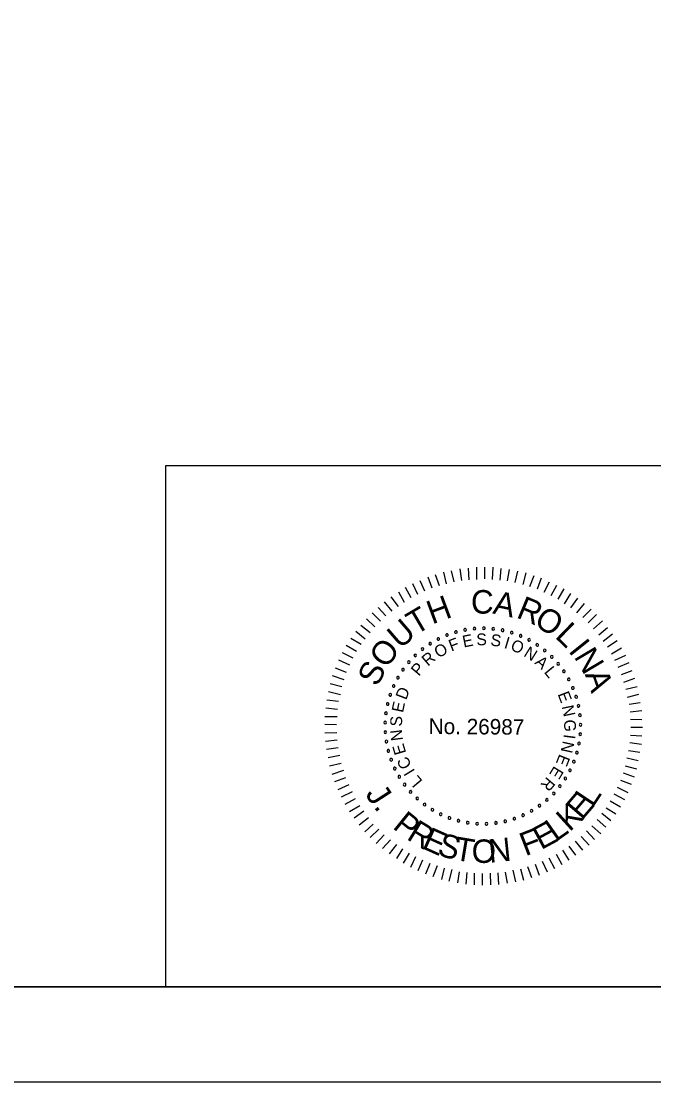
# Model space of a CAD drawing. Extents: x -125.5 to -89.4, y -5.1 to 16.9.
# Drawn here: x -103.66 to -100.32, y -5.07 to 0.53 of the extents above; entities that cross this region are included whole.
import ezdxf

# ---------------------------------------------------------------- set-up
doc = ezdxf.new("R2010")
doc.units = 0
for name, color, linetype in [('BR_BORDER LINES', 7, 'Continuous'), ('BR_TABLE LINES', 7, 'Continuous'), ('BR_TEXT', 7, 'Continuous'), ('Level 31', 7, 'Continuous')]:
    doc.layers.add(name, color=color, linetype=linetype)

msp = doc.modelspace()

# ---------------------------------------------------------------- linework, layer by layer
at = {"layer": 'BR_BORDER LINES'}
for p, q in [((-102.8989, -1.8161), (-97.5337, -1.8161)), ((-102.8989, -4.5661), (-102.8989, -1.8161)), ((-123.6994, -4.5662), (-90.0334, -4.5662))]:
    msp.add_line(p, q, dxfattribs=at)
at = {"layer": 'BR_TABLE LINES'}
msp.add_lwpolyline([(-123.6994, 16.4338), (-90.0334, 16.4338), (-90.0334, -4.5662), (-123.6994, -4.5662)], close=True, dxfattribs=at)
at = {"layer": 'BR_TEXT'}
for p, q in [((-101.4937, -2.4629), (-101.5147, -2.4044)), ((-101.4541, -2.4504), (-101.476, -2.3927)), ((-101.418, -2.4404), (-101.4312, -2.3793)), ((-101.3767, -2.4304), (-101.3908, -2.3711)), ((-101.3372, -2.423), (-101.3461, -2.362)), ((-101.2977, -2.419), (-101.3015, -2.3581)), ((-101.2582, -2.4168), (-101.2576, -2.3524)), ((-101.2161, -2.4146), (-101.2156, -2.3528)), ((-101.1741, -2.4175), (-101.1718, -2.3531)), ((-101.1338, -2.4204), (-101.129, -2.3595)), ((-101.0952, -2.425), (-101.0844, -2.3642)), ((-101.0549, -2.4331), (-101.0407, -2.374)), ((-101.0138, -2.4437), (-100.9979, -2.3829)), ((-100.977, -2.4543), (-100.9551, -2.397)), ((-101.604, -2.5144), (-101.6344, -2.46)), ((-101.5695, -2.4966), (-101.5957, -2.4406)), ((-101.5325, -2.4798), (-101.556, -2.4238)), ((-100.9376, -2.4675), (-100.9157, -2.4093)), ((-100.9017, -2.485), (-100.8738, -2.4294)), ((-100.8658, -2.5024), (-100.8345, -2.4469)), ((-101.6704, -2.5593), (-101.7095, -2.5083)), ((-101.6394, -2.5381), (-101.6698, -2.4838)), ((-100.8282, -2.5208), (-100.796, -2.467)), ((-100.795, -2.5451), (-100.761, -2.4913)), ((-100.7617, -2.5668), (-100.7252, -2.5165)), ((-101.7369, -2.6094), (-101.7786, -2.5644)), ((-101.7041, -2.5847), (-101.744, -2.5346)), ((-100.7293, -2.5928), (-100.6886, -2.5434)), ((-101.7958, -2.6673), (-101.8392, -2.6248)), ((-101.7663, -2.6366), (-101.8106, -2.5925)), ((-100.6977, -2.618), (-100.6545, -2.5737)), ((-100.6697, -2.6456), (-100.6264, -2.6022)), ((-101.8209, -2.6988), (-101.8704, -2.6598)), ((-100.6416, -2.6768), (-100.594, -2.6351)), ((-100.6144, -2.7088), (-100.5677, -2.6705)), ((-101.8686, -2.761), (-101.9224, -2.728)), ((-101.8469, -2.732), (-101.8964, -2.6922)), ((-100.5906, -2.7424), (-100.5414, -2.7033)), ((-100.5686, -2.7718), (-100.516, -2.7396)), ((-101.893, -2.7977), (-101.9467, -2.7656)), ((-100.5466, -2.8089), (-100.4931, -2.7776)), ((-101.9279, -2.8687), (-101.9852, -2.8433)), ((-101.9104, -2.8319), (-101.9668, -2.804)), ((-100.5288, -2.8433), (-100.4711, -2.8164)), ((-101.9454, -2.9072), (-102.0035, -2.8852)), ((-100.5111, -2.8804), (-100.4543, -2.856)), ((-100.4943, -2.9192), (-100.4374, -2.8982)), ((-101.9577, -2.9474), (-102.0193, -2.9246)), ((-100.4809, -2.9596), (-100.4232, -2.9378)), ((-101.9772, -3.0253), (-102.0397, -3.0094)), ((-101.97, -2.9833), (-102.0308, -2.9682)), ((-100.4708, -2.9957), (-100.4107, -2.9816)), ((-101.9878, -3.0613), (-102.0487, -3.0531)), ((-100.4626, -3.0378), (-100.4024, -3.0229)), ((-100.4543, -3.074), (-100.3951, -3.0667)), ((-101.9925, -3.1024), (-102.0542, -3.0951)), ((-100.4478, -3.1152), (-100.3868, -3.1088)), ((-101.9974, -3.183), (-102.06, -3.1825)), ((-101.9954, -3.1419), (-102.0597, -3.1414)), ((-100.4464, -3.1547), (-100.3863, -3.1552)), ((-101.9961, -3.226), (-102.0604, -3.2272)), ((-100.4471, -3.2388), (-100.3871, -3.241)), ((-100.4442, -3.1959), (-100.3833, -3.1964)), ((-101.9938, -3.2646), (-102.0556, -3.2718)), ((-100.4492, -3.2774), (-100.3883, -3.2856)), ((-101.9898, -3.3058), (-102.0509, -3.3148)), ((-101.9799, -3.3454), (-102.0426, -3.3586)), ((-100.4564, -3.3185), (-100.3972, -3.3284)), ((-101.9733, -3.3875), (-102.0344, -3.4016)), ((-100.4742, -3.3999), (-100.4143, -3.415)), ((-100.4653, -3.3579), (-100.4053, -3.3721)), ((-101.9616, -3.4245), (-102.0236, -3.4454)), ((-101.95, -3.4632), (-102.0085, -3.4842)), ((-100.4848, -3.4367), (-100.4275, -3.4586)), ((-101.9331, -3.5003), (-101.9908, -3.5272)), ((-100.5163, -3.512), (-100.4599, -3.5399)), ((-100.4989, -3.4752), (-100.4424, -3.4971)), ((-101.9162, -3.5364), (-101.9731, -3.566)), ((-101.8994, -3.5735), (-101.9537, -3.6048)), ((-100.5346, -3.5479), (-100.4774, -3.5784)), ((-101.8756, -3.6106), (-101.93, -3.6419)), ((-100.5756, -3.6213), (-100.5235, -3.6535)), ((-100.553, -3.5846), (-100.5, -3.6168)), ((-101.8544, -3.6399), (-101.9045, -3.6764)), ((-101.829, -3.6736), (-101.8791, -3.7127)), ((-100.6224, -3.6836), (-100.5764, -3.7234)), ((-100.5981, -3.6503), (-100.5495, -3.6876)), ((-101.8043, -3.7073), (-101.8485, -3.7481)), ((-101.7754, -3.7333), (-101.8204, -3.7784)), ((-100.6787, -3.7423), (-100.6362, -3.7882)), ((-100.6502, -3.7168), (-100.6033, -3.7584)), ((-101.7465, -3.7636), (-101.7889, -3.8095)), ((-101.714, -3.7895), (-101.7548, -3.8364)), ((-100.7392, -3.7976), (-100.6993, -3.8452)), ((-100.7073, -3.7721), (-100.6648, -3.8188)), ((-101.6808, -3.8156), (-101.7207, -3.8633)), ((-101.6501, -3.8373), (-101.6814, -3.8894)), ((-100.8057, -3.8443), (-100.7727, -3.8969)), ((-100.772, -3.8231), (-100.7364, -3.8714)), ((-101.6151, -3.8599), (-101.6464, -3.9137)), ((-101.5809, -3.8799), (-101.608, -3.9355)), ((-101.5442, -3.8974), (-101.5687, -3.953)), ((-100.9135, -3.9026), (-100.8865, -3.9586)), ((-100.8773, -3.8857), (-100.8468, -3.9418)), ((-100.8393, -3.8663), (-100.808, -3.9206)), ((-101.5057, -3.9149), (-101.5276, -3.9713)), ((-101.4663, -3.9272), (-101.4891, -3.9854)), ((-101.4304, -3.9395), (-101.4446, -3.9986)), ((-101.3892, -3.9467), (-101.4044, -4.0084)), ((-101.3499, -3.9582), (-101.3598, -4.0165)), ((-101.3104, -3.9628), (-101.3152, -4.0246)), ((-101.271, -3.9657), (-101.2715, -4.0275)), ((-101.229, -3.9686), (-101.2295, -4.0296)), ((-101.1869, -3.9664), (-101.1857, -4.0282)), ((-101.1466, -3.9642), (-101.1428, -4.026)), ((-101.1079, -3.9602), (-101.098, -4.0186)), ((-101.0675, -3.9494), (-101.0542, -4.0113)), ((-101.0262, -3.9429), (-101.0112, -4.0022)), ((-100.9892, -3.9311), (-100.9682, -3.9897)), ((-100.9496, -3.9194), (-100.9286, -3.9763))]:
    msp.add_line(p, q, dxfattribs=at)
for centre, start, end in [((-101.3196, -2.6831), 10.6038, 190.6038), ((-101.3196, -2.6831), 190.6038, 10.6038), ((-101.2702, -2.6764), 5.0653, 185.0653), ((-101.2702, -2.6764), 185.0653, 5.0653), ((-101.2204, -2.6745), 359.5268, 179.5268), ((-101.2204, -2.6745), 179.5268, 359.5268), ((-101.1707, -2.6774), 173.9884, 353.9884), ((-101.1707, -2.6774), 353.9884, 173.9884), ((-101.1214, -2.6851), 168.4499, 348.4499), ((-101.1214, -2.6851), 348.4499, 168.4499), ((-101.4607, -2.7311), 27.2191, 207.2191), ((-101.4607, -2.7311), 207.2191, 27.2191), ((-101.4153, -2.7106), 21.6807, 201.6807), ((-101.4153, -2.7106), 201.6807, 21.6807), ((-101.3681, -2.6945), 16.1422, 196.1422), ((-101.3681, -2.6945), 196.1422, 16.1422), ((-101.0732, -2.6976), 162.9114, 342.9114), ((-101.0732, -2.6976), 342.9114, 162.9114), ((-101.0263, -2.7146), 157.373, 337.373), ((-101.0263, -2.7146), 337.373, 157.373), ((-100.9814, -2.736), 151.8345, 331.8345), ((-100.9814, -2.736), 331.8345, 151.8345), ((-101.5445, -2.7848), 38.2961, 218.2961), ((-101.5445, -2.7848), 218.2961, 38.2961), ((-101.5039, -2.7559), 32.7576, 212.7576), ((-101.5039, -2.7559), 212.7576, 32.7576), ((-100.9387, -2.7617), 146.2961, 326.2961), ((-100.9387, -2.7617), 326.2961, 146.2961), ((-100.8987, -2.7914), 140.7576, 320.7576), ((-100.8987, -2.7914), 320.7576, 140.7576), ((-101.6164, -2.8536), 49.373, 229.373), ((-101.6164, -2.8536), 229.373, 49.373), ((-101.5821, -2.8175), 43.8345, 223.8345), ((-101.5821, -2.8175), 223.8345, 43.8345), ((-100.8617, -2.8249), 135.2191, 315.2191), ((-100.8617, -2.8249), 315.2191, 135.2191), ((-101.6471, -2.8929), 54.9114, 234.9114), ((-101.6471, -2.8929), 234.9114, 54.9114), ((-100.8282, -2.8617), 129.6807, 309.6807), ((-100.8282, -2.8617), 309.6807, 129.6807), ((-100.7983, -2.9016), 124.1422, 304.1422), ((-100.7983, -2.9016), 304.1422, 124.1422), ((-101.6738, -2.935), 60.4499, 240.4499), ((-101.6738, -2.935), 240.4499, 60.4499), ((-100.7724, -2.9442), 118.6038, 298.6038), ((-100.7724, -2.9442), 298.6038, 118.6038), ((-101.7145, -3.0258), 71.5268, 251.5268), ((-101.7145, -3.0258), 251.5268, 71.5268), ((-101.6964, -2.9794), 65.9884, 245.9884), ((-101.6964, -2.9794), 245.9884, 65.9884), ((-100.7508, -2.9891), 113.0653, 293.0653), ((-100.7508, -2.9891), 293.0653, 113.0653), ((-101.7281, -3.0738), 77.0653, 257.0653), ((-101.7281, -3.0738), 257.0653, 77.0653), ((-100.7336, -3.0359), 107.5268, 287.5268), ((-100.7336, -3.0359), 287.5268, 107.5268), ((-101.737, -3.1228), 82.6038, 262.6038), ((-101.737, -3.1228), 262.6038, 82.6038), ((-100.721, -3.0841), 101.9884, 281.9884), ((-100.721, -3.0841), 281.9884, 101.9884), ((-100.7131, -3.1333), 96.4499, 276.4499), ((-100.7131, -3.1333), 276.4499, 96.4499), ((-101.7411, -3.1724), 88.1422, 268.1422), ((-101.7411, -3.1724), 268.1422, 88.1422), ((-100.71, -3.183), 90.9114, 270.9114), ((-100.71, -3.183), 270.9114, 90.9114), ((-101.7404, -3.2223), 93.6807, 273.6807), ((-101.7404, -3.2223), 273.6807, 93.6807), ((-100.7118, -3.2328), 85.373, 265.373), ((-100.7118, -3.2328), 265.373, 85.373), ((-101.7349, -3.2718), 99.2191, 279.2191), ((-101.7349, -3.2718), 279.2191, 99.2191), ((-100.7183, -3.2822), 79.8345, 259.8345), ((-100.7183, -3.2822), 259.8345, 79.8345), ((-101.7246, -3.3206), 104.7576, 284.7576), ((-101.7246, -3.3206), 284.7576, 104.7576), ((-100.7295, -3.3308), 74.2961, 254.2961), ((-100.7295, -3.3308), 254.2961, 74.2961), ((-101.7097, -3.3681), 110.2961, 290.2961), ((-101.7097, -3.3681), 290.2961, 110.2961), ((-101.6903, -3.414), 115.8345, 295.8345), ((-101.6903, -3.414), 295.8345, 115.8345), ((-100.7454, -3.378), 68.7576, 248.7576), ((-100.7454, -3.378), 248.7576, 68.7576), ((-101.6665, -3.4578), 121.373, 301.373), ((-101.6665, -3.4578), 301.373, 121.373), ((-100.7904, -3.4668), 57.6807, 237.6807), ((-100.7904, -3.4668), 237.6807, 57.6807), ((-100.7658, -3.4235), 63.2191, 243.2191), ((-100.7658, -3.4235), 243.2191, 63.2191), ((-101.6386, -3.4991), 126.9114, 306.9114), ((-101.6386, -3.4991), 306.9114, 126.9114), ((-100.8192, -3.5075), 52.1422, 232.1422), ((-100.8192, -3.5075), 232.1422, 52.1422), ((-101.6069, -3.5375), 132.4499, 312.4499), ((-101.6069, -3.5375), 312.4499, 132.4499), ((-101.5716, -3.5727), 137.9884, 317.9884), ((-101.5716, -3.5727), 317.9884, 137.9884), ((-100.8877, -3.5797), 41.0653, 221.0653), ((-100.8877, -3.5797), 221.0653, 41.0653), ((-100.8517, -3.5452), 46.6038, 226.6038), ((-100.8517, -3.5452), 226.6038, 46.6038), ((-101.5331, -3.6043), 143.5268, 323.5268), ((-101.5331, -3.6043), 323.5268, 143.5268), ((-101.4917, -3.632), 149.0653, 329.0653), ((-101.4917, -3.632), 329.0653, 149.0653), ((-100.9688, -3.6374), 29.9884, 209.9884), ((-100.9688, -3.6374), 209.9884, 29.9884), ((-100.9269, -3.6105), 35.5268, 215.5268), ((-100.9269, -3.6105), 215.5268, 35.5268), ((-101.4478, -3.6556), 154.6038, 334.6038), ((-101.4478, -3.6556), 334.6038, 154.6038), ((-101.4018, -3.6749), 160.1422, 340.1422), ((-101.4018, -3.6749), 340.1422, 160.1422), ((-101.3542, -3.6896), 165.6807, 345.6807), ((-101.3542, -3.6896), 345.6807, 165.6807), ((-101.1074, -3.6921), 13.373, 193.373), ((-101.1074, -3.6921), 193.373, 13.373), ((-101.0595, -3.6784), 18.9114, 198.9114), ((-101.0595, -3.6784), 198.9114, 18.9114), ((-101.0132, -3.6601), 24.4499, 204.4499), ((-101.0132, -3.6601), 204.4499, 24.4499), ((-101.3054, -3.6997), 351.2191, 171.2191), ((-101.3054, -3.6997), 171.2191, 351.2191), ((-101.2559, -3.705), 356.7576, 176.7576), ((-101.2559, -3.705), 176.7576, 356.7576), ((-101.2061, -3.7055), 2.2961, 182.2961), ((-101.2061, -3.7055), 182.2961, 2.2961), ((-101.1564, -3.7012), 7.8345, 187.8345), ((-101.1564, -3.7012), 187.8345, 7.8345)]:
    msp.add_arc(centre, 0.00701, start, end, dxfattribs=at)
at = {"layer": 'Level 31'}
msp.add_lwpolyline([(-125.5328, 16.9339), (-125.5328, -5.0661), (-89.5328, -5.0661), (-89.5328, 16.9339)], dxfattribs=at)

# ---------------------------------------------------------------- texts
at = {"layer": 'BR_TEXT'}
for s, height, rotation, p in [('H', 0.1241, 20.3637, (-101.4933, -2.6552)), ('C', 0.1241, 359.5482, (-101.2889, -2.5969)), ('A', 0.1241, 348.1981, (-101.1775, -2.5961)), ('R', 0.1241, 337.4344, (-101.0542, -2.616)), ('T', 0.1241, 30.4992, (-101.5812, -2.7128)), ('O', 0.1239, 326.5869, (-100.962, -2.6528)), ('U', 0.1241, 40.8022, (-101.6624, -2.7875)), ('L', 0.1241, 315.9488, (-100.8494, -2.7205)), ('O', 0.1241, 52.0267, (-101.7369, -2.8914)), ('F', 0.0622, 20.6127, (-101.392, -2.7981)), ('E', 0.0622, 11.4103, (-101.3269, -2.7764)), ('S', 0.0622, 2.208, (-101.2591, -2.7654)), ('S', 0.0622, 352.6608, (-101.1878, -2.7657)), ('I', 0.0622, 343.1136, (-101.1175, -2.7777)), ('O', 0.0622, 338.4392, (-101.0841, -2.7878)), ('I', 0.1241, 308.6613, (-100.778, -2.7948)), ('O', 0.0622, 30.8477, (-101.4594, -2.8341)), ('N', 0.0622, 328.2042, (-101.0145, -2.8192)), ('N', 0.1241, 300.7037, (-100.7474, -2.8242)), ('S', 0.1239, 63.2511, (-101.7823, -2.9871)), ('R', 0.0622, 40.3949, (-101.5156, -2.878)), ('A', 0.0622, 318.657, (-100.9555, -2.8592)), ('P', 0.0622, 49.9421, (-101.5636, -2.9306)), ('L', 0.0622, 309.4546, (-100.9057, -2.9066)), ('A', 0.1241, 289.4792, (-100.6882, -2.9172)), ('D', 0.0622, 69.0364, (-101.6306, -3.0559)), ('E', 0.0622, 291.049, (-100.8319, -3.0219)), ('E', 0.0622, 78.2388, (-101.6472, -3.1226)), ('N', 0.0622, 281.8466, (-100.8097, -3.0869)), ('S', 0.0622, 87.786, (-101.6529, -3.1936)), ('No. 26987', 0.08175, 359.5268, (-101.5118, -3.232)), ('G', 0.0622, 272.2995, (-100.7979, -3.1572)), ('N', 0.0622, 97.3332, (-101.6467, -3.2646)), ('I', 0.0622, 262.4084, (-100.7983, -3.231)), ('E', 0.0622, 106.5355, (-101.6297, -3.3312)), ('N', 0.0622, 257.7339, (-100.8028, -3.2656)), ('C', 0.0622, 116.4266, (-101.5998, -3.3987)), ('E', 0.0622, 248.1867, (-100.8209, -3.3346)), ('E', 0.0622, 238.9844, (-100.8488, -3.3973)), ('I', 0.0622, 121.1011, (-101.5818, -3.4285)), ('L', 0.0622, 129.9595, (-101.5411, -3.4807)), ('R', 0.0622, 229.782, (-100.8865, -3.4548)), ('J', 0.1236, 302.9559, (-101.849, -3.5492)), ('E', 0.1236, 49.3639, (-100.703, -3.6911)), ('L', 0.1236, 56.4247, (-100.6455, -3.6233)), ('.', 0.1236, 309.3974, (-101.8049, -3.6172)), ('K', 0.1236, 42.3031, (-100.7683, -3.7512)), ('P', 0.1236, 321.1035, (-101.7065, -3.7264)), ('R', 0.1236, 328.5359, (-101.6332, -3.7844)), ('E', 0.1236, 28.1814, (-100.9186, -3.8452)), ('L', 0.1236, 35.2422, (-100.8406, -3.8028)), ('E', 0.1236, 335.9684, (-101.5531, -3.8325)), ('F', 0.1236, 21.1206, (-101.0013, -3.8776)), ('S', 0.1236, 343.0292, (-101.4718, -3.8682)), ('T', 0.1236, 350.4617, (-101.3821, -3.8947)), ('O', 0.1236, 358.1419, (-101.2867, -3.9097)), ('N', 0.1236, 5.8221, (-101.1902, -3.9118))]:
    msp.add_text(s, height=height, rotation=rotation, dxfattribs=at).set_placement(p)

doc.saveas('drawing.dxf')
